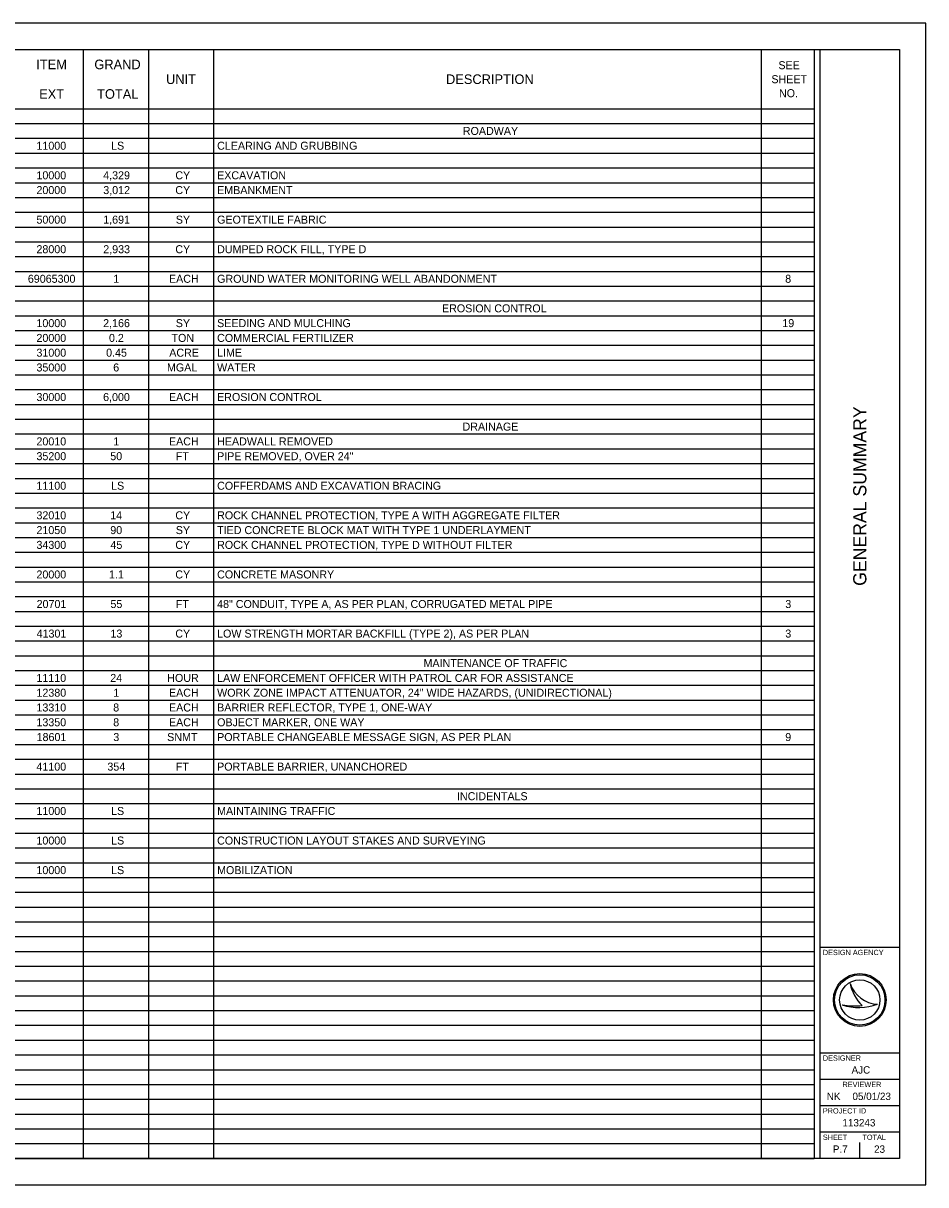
# Model space of a CAD drawing. Extents: x 0 to 34, y 0 to 22.
# Drawn here: x 16.9 to 34, y 0 to 22 of the extents above; entities that cross this region are included whole.
import ezdxf

# ---------------------------------------------------------------- set-up
doc = ezdxf.new("R2010")
doc.units = 0
for name, color, linetype in [('SH_Border', 7, 'Continuous'), ('SH_Cut_Line', 7, 'Continuous'), ('SH_Data', 7, 'Continuous'), ('SH_Text', 7, 'Continuous')]:
    doc.layers.add(name, color=color, linetype=linetype)

msp = doc.modelspace()

# ---------------------------------------------------------------- linework, layer by layer
at = {"layer": 'SH_Border'}
for p, q in [((32, 0.5), (32, 21.5)), ((32, 4.5), (33.5, 4.5)), ((32, 2.5), (33.5, 2.5)), ((32, 2), (33.5, 2)), ((32, 1.5), (33.5, 1.5)), ((32, 1), (33.5, 1))]:
    msp.add_line(p, q, dxfattribs=at)
msp.add_lwpolyline([(1.5, 21.5), (33.5, 21.5), (33.5, 0.5), (1.5, 0.5)], close=True, dxfattribs=at)
at = {"layer": 'SH_Cut_Line'}
msp.add_lwpolyline([(0, 0), (34, 0), (34, 22), (0, 22)], close=True, dxfattribs=at)
at = {"layer": 'SH_Data'}
for p, q in [((32.567, 3.81), (32.567, 3.81)), ((32.417, 3.41), (32.417, 3.41)), ((32.75, 3.5), (32.75, 3.5)), ((33.087, 3.419), (33.087, 3.419)), ((32.375, 0.675), (32.375, 0.675)), ((32.75, 0.5), (32.75, 0.8))]:
    msp.add_line(p, q, dxfattribs=at)
for radius in [0.5, 0.477, 0.477, 0.382]:
    msp.add_circle((32.75, 3.5), radius, dxfattribs=at)
for centre, radius, start, end in [((33.116, 3.998), 0.58, 198.9257, 198.9319), ((33.347, 3.97), 0.796, 191.6379, 191.6421), ((33.116, 3.998), 0.58, 198.9319, 267.1657), ((33.347, 3.97), 0.796, 191.6421, 226.0947), ((32.739, 4.37), 1.013, 251.4576, 290.0832), ((32.648, 4.654), 1.266, 259.4964, 259.4995), ((32.739, 4.37), 1.013, 251.4527, 251.4576), ((32.648, 4.654), 1.266, 259.4995, 276.6672)]:
    msp.add_arc(centre, radius, start, end, dxfattribs=at)
at = {"layer": 'SH_Text'}
for p, q in [((1.5, 21.5), (31.888, 21.5)), ((18.036, 21.5), (18.036, 0.5)), ((19.272, 21.5), (19.272, 0.5)), ((20.507, 21.5), (20.507, 0.5)), ((30.884, 21.5), (30.884, 0.5)), ((31.888, 21.5), (31.888, 0.5)), ((1.5, 20.38), (31.888, 20.38)), ((1.5, 20.1), (31.888, 20.1)), ((1.5, 19.82), (31.888, 19.82)), ((1.5, 19.54), (31.888, 19.54)), ((1.5, 19.26), (31.888, 19.26)), ((1.5, 18.98), (31.888, 18.98)), ((1.5, 18.7), (31.888, 18.7)), ((1.5, 18.42), (31.888, 18.42)), ((1.5, 18.14), (31.888, 18.14)), ((1.5, 17.86), (31.888, 17.86)), ((1.5, 17.58), (31.888, 17.58)), ((1.5, 17.3), (31.888, 17.3)), ((1.5, 17.02), (31.888, 17.02)), ((1.5, 16.74), (31.888, 16.74)), ((1.5, 16.46), (31.888, 16.46)), ((1.5, 16.18), (31.888, 16.18)), ((1.5, 15.9), (31.888, 15.9)), ((1.5, 15.62), (31.888, 15.62)), ((1.5, 15.34), (31.888, 15.34)), ((1.5, 15.06), (31.888, 15.06)), ((1.5, 14.78), (31.888, 14.78)), ((1.5, 14.5), (31.888, 14.5)), ((1.5, 14.22), (31.888, 14.22)), ((1.5, 13.94), (31.888, 13.94)), ((1.5, 13.66), (31.888, 13.66)), ((1.5, 13.38), (31.888, 13.38)), ((1.5, 13.1), (31.888, 13.1)), ((1.5, 12.82), (31.888, 12.82)), ((1.5, 12.54), (31.888, 12.54)), ((1.5, 12.26), (31.888, 12.26)), ((1.5, 11.98), (31.888, 11.98)), ((1.5, 11.7), (31.888, 11.7)), ((1.5, 11.42), (31.888, 11.42)), ((1.5, 11.14), (31.888, 11.14)), ((1.5, 10.86), (31.888, 10.86)), ((1.5, 10.58), (31.888, 10.58)), ((1.5, 10.3), (31.888, 10.3)), ((1.5, 10.02), (31.888, 10.02)), ((1.5, 9.74), (31.888, 9.74)), ((1.5, 9.46), (31.888, 9.46)), ((1.5, 9.18), (31.888, 9.18)), ((1.5, 8.9), (31.888, 8.9)), ((1.5, 8.62), (31.888, 8.62)), ((1.5, 8.34), (31.888, 8.34)), ((1.5, 8.06), (31.888, 8.06)), ((1.5, 7.78), (31.888, 7.78)), ((1.5, 7.5), (31.888, 7.5)), ((1.5, 7.22), (31.888, 7.22)), ((1.5, 6.94), (31.888, 6.94)), ((1.5, 6.66), (31.888, 6.66)), ((1.5, 6.38), (31.888, 6.38)), ((1.5, 6.1), (31.888, 6.1)), ((1.5, 5.82), (31.888, 5.82)), ((1.5, 5.54), (31.888, 5.54)), ((1.5, 5.26), (31.888, 5.26)), ((1.5, 4.98), (31.888, 4.98)), ((1.5, 4.7), (31.888, 4.7)), ((1.5, 4.42), (31.888, 4.42)), ((1.5, 4.14), (31.888, 4.14)), ((1.5, 3.86), (31.888, 3.86)), ((1.5, 3.58), (31.888, 3.58)), ((1.5, 3.3), (31.888, 3.3)), ((1.5, 3.02), (31.888, 3.02)), ((1.5, 2.74), (31.888, 2.74)), ((1.5, 2.46), (31.888, 2.46)), ((1.5, 2.18), (31.888, 2.18)), ((1.5, 1.9), (31.888, 1.9)), ((1.5, 1.62), (31.888, 1.62)), ((1.5, 1.34), (31.888, 1.34)), ((1.5, 1.06), (31.888, 1.06)), ((1.5, 0.78), (31.888, 0.78)), ((1.5, 0.5), (31.888, 0.5))]:
    msp.add_line(p, q, dxfattribs=at)

# ---------------------------------------------------------------- texts
at = {"layer": 'SH_Data'}
msp.add_text('GENERAL SUMMARY', height=0.25, rotation=90, dxfattribs=at).set_placement((32.875, 11.344))
for s, height, p in [('DESIGN AGENCY', 0.1, (32.05, 4.35)), ('DESIGNER', 0.1, (32.05, 2.35)), ('AJC', 0.14, (32.594, 2.105)), ('REVIEWER', 0.1, (32.422, 1.85)), ('NK', 0.14, (32.124, 1.605)), ('05/01/23', 0.14, (32.611, 1.605)), ('PROJECT ID', 0.1, (32.05, 1.35)), ('113243', 0.14, (32.421, 1.105)), ('SHEET', 0.1, (32.05, 0.85)), ('TOTAL', 0.1, (32.8, 0.85)), ('P.7', 0.14, (32.239, 0.605)), ('23', 0.14, (33.02, 0.605))]:
    msp.add_text(s, height=height, dxfattribs=at).set_placement(p)
at = {"layer": 'SH_Text'}
for s, height, p in [('ITEM', 0.1818, (17.147, 21.129)), ('GRAND', 0.1818, (18.247, 21.129)), ('SEE ', 0.1515, (31.208, 21.129)), ('UNIT', 0.1818, (19.606, 20.849)), ('DESCRIPTION', 0.18184, (24.91, 20.849)), ('SHEET ', 0.1515, (31.075, 20.864)), ('EXT', 0.1818, (17.201, 20.569)), ('TOTAL', 0.1818, (18.299, 20.569)), ('NO.', 0.1515, (31.219, 20.599)), ('ROADWAY', 0.1515, (25.229, 19.884)), ('11000', 0.1515, (17.15, 19.604)), ('LS', 0.1515, (18.564, 19.604)), ('CLEARING AND GRUBBING', 0.15153, (20.573, 19.604)), ('10000', 0.1515, (17.15, 19.044)), ('4,329', 0.1515, (18.415, 19.044)), ('CY', 0.1515, (19.781, 19.044)), ('EXCAVATION', 0.1515, (20.573, 19.044)), ('20000', 0.1515, (17.15, 18.764)), ('3,012', 0.1515, (18.416, 18.764)), ('CY', 0.1515, (19.781, 18.764)), ('EMBANKMENT', 0.1515, (20.573, 18.764)), ('50000', 0.1515, (17.15, 18.204)), ('1,691', 0.1515, (18.415, 18.204)), ('SY', 0.1515, (19.79, 18.204)), ('GEOTEXTILE FABRIC', 0.15153, (20.573, 18.204)), ('28000', 0.1515, (17.15, 17.644)), ('2,933', 0.1515, (18.416, 17.644)), ('CY', 0.1515, (19.781, 17.644)), ('DUMPED ROCK FILL, TYPE D', 0.15153, (20.573, 17.644)), ('69065300', 0.1515, (16.987, 17.084)), ('1', 0.152, (18.606, 17.084)), ('EACH', 0.1515, (19.661, 17.084)), ('GROUND WATER MONITORING WELL ABANDONMENT', 0.15153, (20.573, 17.084)), ('8', 0.152, (31.336, 17.084)), ('EROSION CONTROL', 0.15153, (24.834, 16.524)), ('10000', 0.1515, (17.15, 16.244)), ('2,166', 0.1515, (18.414, 16.244)), ('SY', 0.1515, (19.79, 16.244)), ('SEEDING AND MULCHING', 0.15153, (20.573, 16.244)), ('19', 0.1515, (31.282, 16.244)), ('20000', 0.1515, (17.15, 15.964)), ('0.2', 0.1515, (18.524, 15.964)), ('TON', 0.1515, (19.709, 15.964)), ('COMMERCIAL FERTILIZER', 0.15153, (20.573, 15.964)), ('31000', 0.1515, (17.15, 15.684)), ('0.45', 0.1515, (18.47, 15.684)), ('ACRE', 0.1515, (19.666, 15.684)), ('LIME', 0.1515, (20.573, 15.684)), ('35000', 0.1515, (17.15, 15.404)), ('6', 0.152, (18.604, 15.404)), ('MGAL', 0.1515, (19.623, 15.404)), ('WATER', 0.1515, (20.573, 15.404)), ('30000', 0.1515, (17.15, 14.844)), ('6,000', 0.1515, (18.413, 14.844)), ('EACH', 0.1515, (19.661, 14.844)), ('EROSION CONTROL', 0.15153, (20.573, 14.844)), ('DRAINAGE', 0.1515, (25.223, 14.284)), ('20010', 0.1515, (17.15, 14.004)), ('1', 0.152, (18.606, 14.004)), ('EACH', 0.1515, (19.661, 14.004)), ('HEADWALL REMOVED', 0.15153, (20.573, 14.004)), ('35200', 0.1515, (17.15, 13.724)), ('50', 0.1515, (18.549, 13.724)), ('FT', 0.1515, (19.789, 13.724)), ('PIPE REMOVED, OVER 24"', 0.15153, (20.573, 13.724)), ('11100', 0.1515, (17.15, 13.164)), ('LS', 0.1515, (18.564, 13.164)), ('COFFERDAMS AND EXCAVATION BRACING', 0.15153, (20.573, 13.164)), ('32010', 0.1515, (17.15, 12.604)), ('14', 0.1515, (18.548, 12.604)), ('CY', 0.1515, (19.781, 12.604)), ('ROCK CHANNEL PROTECTION, TYPE A WITH AGGREGATE FILTER', 0.15153, (20.573, 12.604)), ('21050', 0.1515, (17.15, 12.324)), ('90', 0.1515, (18.549, 12.324)), ('SY', 0.1515, (19.79, 12.324)), ('TIED CONCRETE BLOCK MAT WITH TYPE 1 UNDERLAYMENT', 0.15153, (20.573, 12.324)), ('34300', 0.1515, (17.15, 12.044)), ('45', 0.1515, (18.552, 12.044)), ('CY', 0.1515, (19.781, 12.044)), ('ROCK CHANNEL PROTECTION, TYPE D WITHOUT FILTER', 0.15153, (20.573, 12.044)), ('20000', 0.1515, (17.15, 11.484)), ('1.1', 0.1515, (18.524, 11.484)), ('CY', 0.1515, (19.781, 11.484)), ('CONCRETE MASONRY', 0.15153, (20.573, 11.484)), ('20701', 0.1515, (17.153, 10.924)), ('55', 0.1515, (18.552, 10.924)), ('FT', 0.1515, (19.789, 10.924)), ('48" CONDUIT, TYPE A, AS PER PLAN, CORRUGATED METAL PIPE', 0.15153, (20.573, 10.924)), ('3', 0.152, (31.338, 10.924)), ('41301', 0.1515, (17.153, 10.364)), ('13', 0.1515, (18.552, 10.364)), ('CY', 0.1515, (19.781, 10.364)), ('LOW STRENGTH MORTAR BACKFILL (TYPE 2), AS PER PLAN', 0.15153, (20.573, 10.364)), ('3', 0.152, (31.338, 10.364)), ('MAINTENANCE OF TRAFFIC', 0.15153, (24.484, 9.804)), ('11110', 0.1515, (17.15, 9.524)), ('24', 0.1515, (18.548, 9.524)), ('HOUR', 0.1515, (19.628, 9.524)), ('LAW ENFORCEMENT OFFICER WITH PATROL CAR FOR ASSISTANCE', 0.15153, (20.573, 9.524)), ('12380', 0.1515, (17.15, 9.244)), ('1', 0.152, (18.606, 9.244)), ('EACH', 0.1515, (19.661, 9.244)), ('WORK ZONE IMPACT ATTENUATOR, 24" WIDE HAZARDS, (UNIDIRECTIONAL)', 0.15153, (20.573, 9.244)), ('13310', 0.1515, (17.15, 8.964)), ('8', 0.152, (18.604, 8.964)), ('EACH', 0.1515, (19.661, 8.964)), ('BARRIER REFLECTOR, TYPE 1, ONE-WAY', 0.15153, (20.573, 8.964)), ('13350', 0.1515, (17.15, 8.684)), ('8', 0.152, (18.604, 8.684)), ('EACH', 0.1515, (19.661, 8.684)), ('OBJECT MARKER, ONE WAY', 0.15153, (20.573, 8.684)), ('18601', 0.1515, (17.153, 8.404)), ('3', 0.152, (18.606, 8.404)), ('SNMT', 0.1515, (19.627, 8.404)), ('PORTABLE CHANGEABLE MESSAGE SIGN, AS PER PLAN', 0.15153, (20.573, 8.404)), ('9', 0.152, (31.337, 8.404)), ('41100', 0.1515, (17.15, 7.844)), ('354', 0.1515, (18.494, 7.844)), ('FT', 0.1515, (19.789, 7.844)), ('PORTABLE BARRIER, UNANCHORED', 0.15153, (20.573, 7.844)), ('INCIDENTALS', 0.15153, (25.117, 7.284)), ('11000', 0.1515, (17.15, 7.004)), ('LS', 0.1515, (18.564, 7.004)), ('MAINTAINING TRAFFIC', 0.15153, (20.573, 7.004)), ('10000', 0.1515, (17.15, 6.444)), ('LS', 0.1515, (18.564, 6.444)), ('CONSTRUCTION LAYOUT STAKES AND SURVEYING', 0.15153, (20.573, 6.444)), ('10000', 0.1515, (17.15, 5.884)), ('LS', 0.1515, (18.564, 5.884)), ('MOBILIZATION', 0.15153, (20.573, 5.884))]:
    msp.add_text(s, height=height, dxfattribs=at).set_placement(p)

doc.saveas('drawing.dxf')
